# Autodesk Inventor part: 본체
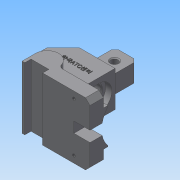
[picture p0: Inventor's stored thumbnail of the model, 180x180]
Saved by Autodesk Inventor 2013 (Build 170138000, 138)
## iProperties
Created: 2016-11
Part Number: 본체
Material: 일반
Document SubType Name: Modeling
Designer: Administrator
Density: 1 g/cm^3
Author: Administrator
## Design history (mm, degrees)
sketch "스케치1"
  geometry: L1 (-27, 0)-(-27, -30); L2 (-27, -30)-(31, -30); L3 (31, -30)-(31, 18); L4 (31, 18)-(-9, 18); L5 (-9, 18)-(-27, 0); 1 further point
  constraints: 10 end point, 1 horizontal, 1 parallel, 1 perpendicular, 1 vertical
  dimensions: "d3" = 30 distance from line of point (0, 0) L2; "d4" = 27 distance from line of point (0, 0) L1; "d7" = 45 deg angle of L5 L4; "d8" = 58 distance between parallel lines of L3 L1; "d9" = 18 distance from line of L4.end L1; "d10" = 48 distance between parallel lines of L2 L4
extrude "돌출1" new body sketch "스케치1" stored distance "d11" = 40; taper "d12" = 0 deg
sketch "스케치3"
  geometry: C1 r 14.5 at (20, 30); 1 further point
  constraints: 1 centre point, 1 coincident
  dimensions: "d13" = 29 diameter of C1
extrude "돌출2" cut sketch "스케치3" distance "d14" = 7; taper "d15" = 0 deg
sketch "스케치4"
  geometry: C1 r 14.5 at (0, 0) reference; C2 r 10 at (0, 0)
  constraints: 1 centre point, 1 coincident
  dimensions: "d16" = 20 diameter of C2
extrude "돌출3" cut sketch "스케치4" stored distance "d17" = 7; taper "d18" = 0 deg
sketch "스케치6"
  geometry: L1 (31, 14.5)-(24, 14.5) reference; L2 (24, 14.5)-(24, 10) reference; L3 (24, 10)-(-17, 10) reference; L4 (-17, 10)-(-9, 18) reference; L5 (-9, 18)-(31, 18) reference; L6 (31, 18)-(31, 14.5) reference; L7 (24, -14.5)-(31, -14.5) reference; L8 (31, -14.5)-(31, -30) reference; L9 (31, -30)-(-27, -30) reference; L10 (-27, -30)-(-27, -10) reference; L11 (-27, -10)-(24, -10) reference; L12 (24, -10)-(24, -14.5) reference; L13 (17.292, -27)-(63, -27); L14 (-13, -27)-(-13, -42); L15 (-13, -42)-(-10, -42); L16 (-10, -42)-(-10, -35); L17 (-10, -35)-(10, -35); L18 (10, -35)-(10, -42); L19 (10, -42)-(63, -42); L20 (63, -42)-(63, -27); A1 r 13 centre (0, -27) between (12.488, -23.389) and (-13, -27); A2 r 5 centre (17.292, -22) between (12.488, -23.389) and (17.292, -27); 1 further point
  constraints: 16 end point, 4 point on circle, 3 parallel, 3 perpendicular, 3 tangent, 2 centre point, 2 collinear, 1 vertical
  dimensions: "d21" = 90 distance between parallel lines of L20 L10; "d22" = 7 distance between parallel lines of L15 L17; "d23" = 3 distance between parallel lines of L16 L14; "d24" = 20 distance between parallel lines of L18 L16; "d25" = 63 distance from line of L20 A1.centre; "d26" = 15 distance between parallel lines of L19 L13; "d27" = 60 distance between parallel lines of L15 L5; "d28" = 5 radius of A2; "d29" = 13 radius of A1; "d30" = 15 distance from line of L19 A1.centre
extrude "돌출4" join sketch "스케치6" stored distance "d31" = 70; taper "d32" = 0 deg
sketch "스케치7"
  geometry: L1 (24, 10)-(-17, 10) reference; L2 (-17, 10)-(-9, 18) reference; L3 (-9, 18)-(31, 18) reference; L4 (31, 18)-(31, 14.5) reference; L5 (31, 14.5)-(24, 14.5) reference; L6 (24, 14.5)-(24, 10) reference; L7 (-27, -10)-(24, -10) reference; L8 (24, -10)-(24, -14.5) reference; L9 (24, -14.5)-(31, -14.5) reference; L10 (31, -14.5)-(31, -27) reference; L11 (31, -27)-(63, -27) reference; L12 (63, -27)-(63, -42) reference; L13 (63, -42)-(10, -42) reference; L14 (10, -42)-(10, -35) reference; L15 (10, -35)-(-10, -35) reference; L16 (-10, -35)-(-10, -42) reference; L17 (-10, -42)-(-13, -42) reference; L18 (-13, -42)-(-13, -30) reference; L19 (-13, -30)-(-27, -30) reference; L20 (-27, -30)-(-27, -10) reference; L21 (26, 18)-(1, 18); L22 (1, 18)-(1, 48); L23 (1, 48)-(26, 48); L24 (26, 48)-(26, 18); 2 further points
  constraints: 8 end point, 2 parallel, 1 horizontal, 1 midpoint, 1 perpendicular, 1 point on line
  dimensions: "d33" = 90 distance between parallel lines of L23 L13; "d34" = 25 distance of L22.end L23.end; "d35" = 5 distance between parallel lines of L24 L4
extrude "돌출5" join sketch "스케치7" stored distance "d36" = 20; taper "d37" = 0 deg
sketch "스케치9"
  geometry: L1 (24, 10)-(-17, 10) reference; L2 (-17, 10)-(-9, 18) reference; L3 (-9, 18)-(1, 18) reference; L4 (1, 18)-(1, 48) reference; L5 (1, 48)-(26, 48) reference; L6 (26, 48)-(26, 18) reference; L7 (26, 18)-(31, 18) reference; L8 (31, 18)-(31, 14.5) reference; L9 (31, 14.5)-(24, 14.5) reference; L10 (24, 14.5)-(24, 10) reference; L11 (-27, -10)-(24, -10) reference; L12 (24, -10)-(24, -14.5) reference; L13 (24, -14.5)-(31, -14.5) reference; L14 (31, -14.5)-(31, -27) reference; L15 (31, -27)-(63, -27) reference; L16 (63, -27)-(63, -42) reference; L17 (63, -42)-(10, -42) reference; L18 (10, -42)-(10, -35) reference; L19 (10, -35)-(-10, -35) reference; L20 (-10, -35)-(-10, -42) reference; L21 (-10, -42)-(-13, -42) reference; L22 (-13, -42)-(-13, -30) reference; L23 (-13, -30)-(-27, -30) reference; L24 (-27, -30)-(-27, -10) reference; C1 r 4 at (13.5, 35); 1 further point
  constraints: 1 centre point
  dimensions: "d40" = 8 diameter of C1; "d41" = 35 vertical distance of point (0, 0) C1.centre; "d42" = 12.5 distance from line of C1.centre L4
extrude "돌출6" cut sketch "스케치9" stored distance "d43" = 20; taper "d44" = 0 deg
sketch "스케치13"
  geometry: L1 (24, 10)-(-17, 10) reference; L2 (-17, 10)-(-9, 18) reference; L3 (-9, 18)-(1, 18) reference; L4 (1, 18)-(1, 48) reference; L5 (1, 48)-(26, 48) reference; L6 (26, 48)-(26, 18) reference; L7 (26, 18)-(31, 18) reference; L8 (31, 18)-(31, 14.5) reference; L9 (31, 14.5)-(24, 14.5) reference; L10 (24, 14.5)-(24, 10) reference; L11 (-27, -10)-(24, -10) reference; L12 (24, -10)-(24, -14.5) reference; L13 (24, -14.5)-(31, -14.5) reference; L14 (31, -14.5)-(31, -27) reference; L15 (31, -27)-(63, -27) reference; L16 (63, -27)-(63, -42) reference; L17 (63, -42)-(10, -42) reference; L18 (10, -42)-(10, -35) reference; L19 (10, -35)-(-10, -35) reference; L20 (-10, -35)-(-10, -42) reference; L21 (-10, -42)-(-13, -42) reference; L22 (-13, -42)-(-13, -30) reference; L23 (-13, -30)-(-27, -30) reference; L24 (-27, -30)-(-27, -10) reference; L25 (31, -27)-(63, -27); L26 (63, -27)-(63, -22); L27 (63, -22)-(31, -22); L28 (31, -22)-(31, -27); C1 r 4 at (13.5, 35) reference; 1 further point
  constraints: 8 end point, 2 parallel, 1 horizontal, 1 perpendicular
  dimensions: "d45" = 90 distance between parallel lines of L26 L24; "d46" = 20 distance between parallel lines of L17 L27
extrude "돌출7" join sketch "스케치13" stored distance "d47" = 40; taper "d48" = 0 deg
sketch "스케치17"
  geometry: L1 (70, 0)-(0, 0) reference; L2 (55, 20)-(15, 20) reference; L3 (41, 13.627)-(41, 0); L4 (41, 0)-(29, 0); L5 (29, 0)-(29, 13.627); A1 r 29 centre (35, 42) between (41, 13.627) and (53.894, 20); A2 r 29 centre (35, 42) between (16.106, 20) and (29, 13.627); 2 further points
  constraints: 6 end point, 4 point on circle, 2 centre point, 2 midpoint, 2 parallel, 2 point on line, 1 coincident, 1 vertical alignment
  dimensions: "d63" = 12 distance between parallel lines of L3 L5; "d65" = 29 radius of A2; "d66" = 29 radius of A1; "d67" = 13.62748 distance of L4.end L5.end
extrude "돌출9" cut sketch "스케치17" distance "d68" = 18; taper "d69" = 0 deg
sketch "스케치18"
  geometry: L1 (45.708, -15)-(0, -15) reference; L2 (45.708, -15)-(45.708, 0) reference; 2 further points
  dimensions: "d70" = 18 distance from line of point (27.708, -7.5) L2; "d71" = 7.5 distance from line of point (27.708, -7.5) L1
hole "구멍1" sketch "스케치18" at (27.708, -7.5) diameter "d72" = 3.242; stored, may be unused: countersink angle "d76" = 90 deg, drill point angle "d78" = 0 deg; dims "d73" = 6, "d74" = 4, "d75" = 2, "d77" = 8
chamfer "모따기1" distance "d79" = 4; stored, may be unused: second distance "d80" = 2, angle "d81" = 45 deg
chamfer "모따기2" distance "d82" = 1; stored, may be unused: second distance "d83" = 2, angle "d84" = 45 deg
chamfer "모따기3" distance "d85" = 4; stored, may be unused: second distance "d86" = 2, angle "d87" = 45 deg
fillet "모깎기1" dims "d88" = 3
chamfer "모따기4" distance "d89" = 5; stored, may be unused: second distance "d90" = 2, angle "d91" = 45 deg
sketch "스케치19"
  geometry: L1 (31, -19)-(31, 18) reference; L2 (31, 18)-(-9, 18) reference; 2 further points
  constraints: 1 other
  dimensions: "d92" = 25 distance from line of point (6, 0) L1; "d93" = 18 distance from line of point (6, 0) L2
feature "엠보싱1" sketch "스케치19" dims "d4" = 27, "d94" = 0.5, "d95" = 0
node "솔리드1"
mirror "대칭1"
node "절단 모서리 투영2"
node "절단 모서리 투영3"
node "절단 모서리 투영4"
node "절단 모서리 투영5"
other parameters: "d49" = 58, "d62" = 58
